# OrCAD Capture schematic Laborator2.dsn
size A
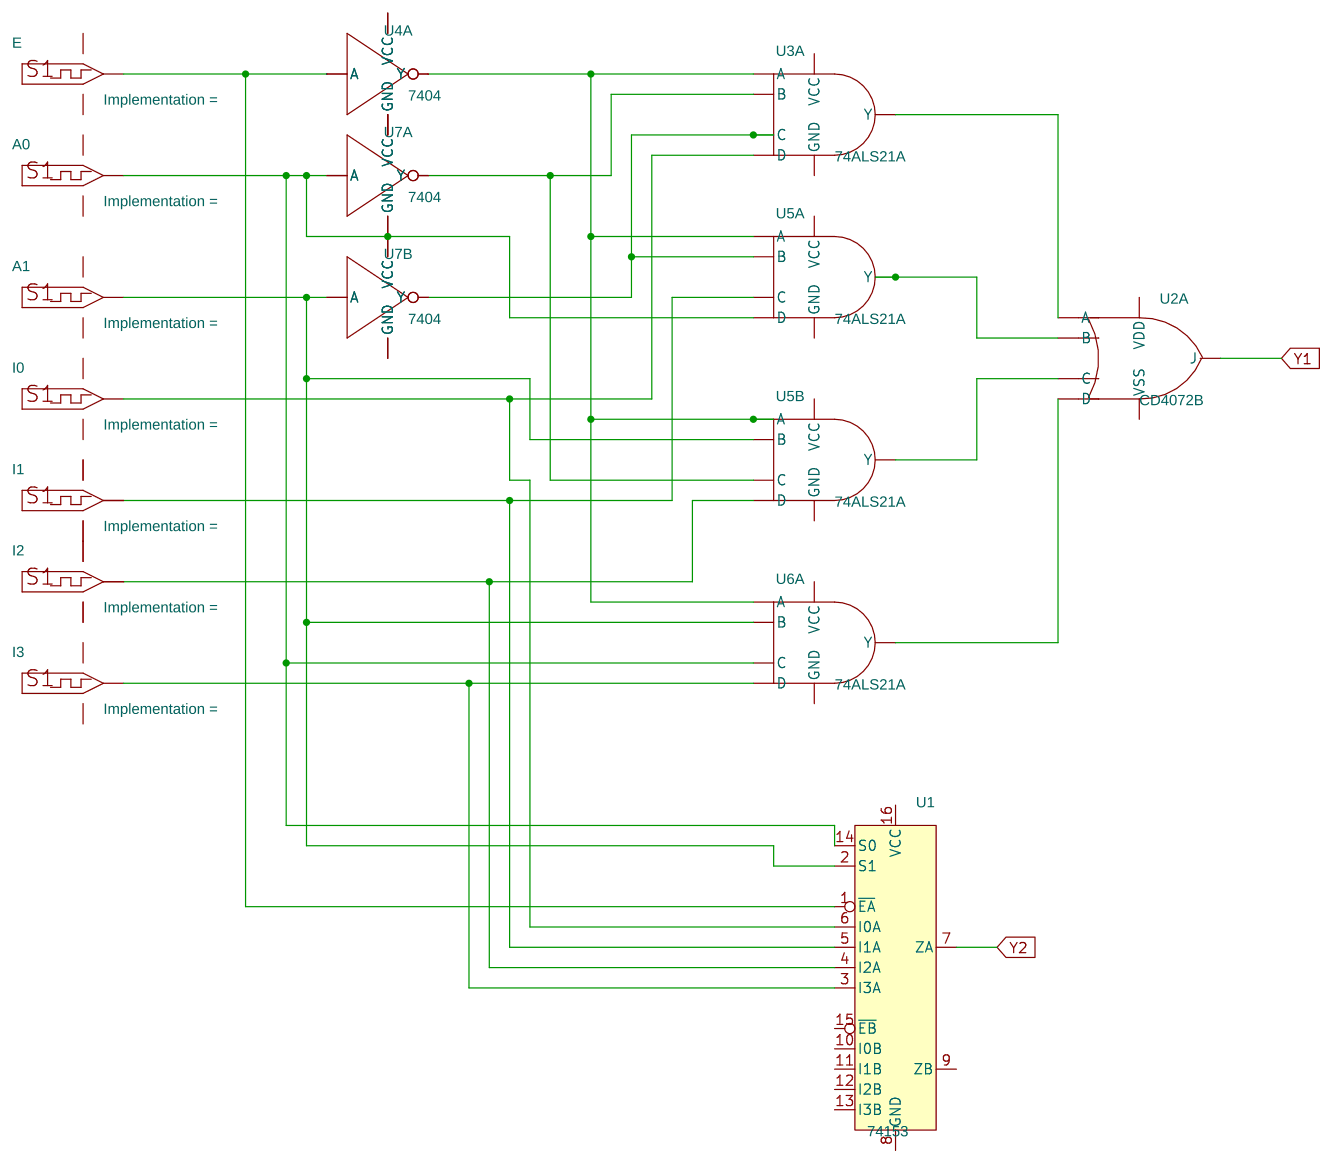
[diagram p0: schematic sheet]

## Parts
A0  DigStim1
A1  DigStim1
E  DigStim1
I0  DigStim1
I1  DigStim1
I2  DigStim1
I3  DigStim1
U1  74153  [DIP.100/16/W.300/L.900]
U2  CD4072B  [DIP.100/14/W.300/L.800]  (section A)
U3  74ALS21A  [DIP.100/14/W.300/L.800]  (section A)
U4  7404  [DIP.100/14/W.300/L.800]  (section A)
U5  74ALS21A  [DIP.100/14/W.300/L.800]  (sections A,B)
U6  74ALS21A  [DIP.100/14/W.300/L.800]  (section A)
U7  7404  [DIP.100/14/W.300/L.800]  (sections A,B)

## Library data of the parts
A0 A1 E I0-I3 = DigStim1
U1 = 74153
U2 = CD4072B
U3 U5 U6 = 74ALS21A
U4 U7 = 7404

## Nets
GND: A0.3(GND) A1.3(GND) E.3(GND) I0.3(GND) I1.3(GND) I2.3(GND) I3.3(GND) U1.8(GND) U3.7(GND) U4.7(GND) U5.7(GND) U6.7(GND) U7.7(GND)
VCC: A0.2(VCC) A1.2(VCC) E.2(VCC) I0.2(VCC) I1.2(VCC) I2.2(VCC) I3.2(VCC) U1.16(VCC) U3.14(VCC) U4.14(VCC) U5.14(VCC) U6.14(VCC) U7.14(VCC)
VDD: U2.14(VDD)
VSS: U2.7(VSS)
Y1: U2.1(J)
Y2: U1.7(ZA)
N15337: E.OUT U1.1(~{EA}) U4.1(A)
N15492: A1.OUT U1.2(S1) U5.10(B) U6.2(B) U7.3(A)
N15502: A0.OUT U1.14(S0) U5.5(D) U6.4(C) U7.1(A)
N15675: U3.1(A) U4.2(Y) U5.1(A) U5.9(A) U6.1(A)
N15730: U3.2(B) U5.12(C) U7.2(Y)
N15742: U3.4(C) U5.2(B) U7.4(Y)
N15759: I0.OUT U1.6(I0A) U3.5(D)
N15816: I1.OUT U1.5(I1A) U5.4(C)
N15875: I2.OUT U1.4(I2A) U5.13(D)
N15887: I3.OUT U1.3(I3A) U6.5(D)
N15992: U2.5(D) U6.6(Y)
N15999: U2.2(A) U3.6(Y)
N16006: U2.3(B) U5.6(Y)
N16026: U2.4(C) U5.8(Y)

Not connected (* = marked no-connect by the designer): U1 9(ZB) 10(I0B) 11(I1B) 12(I2B) 13(I3B) 15(~{EB})
